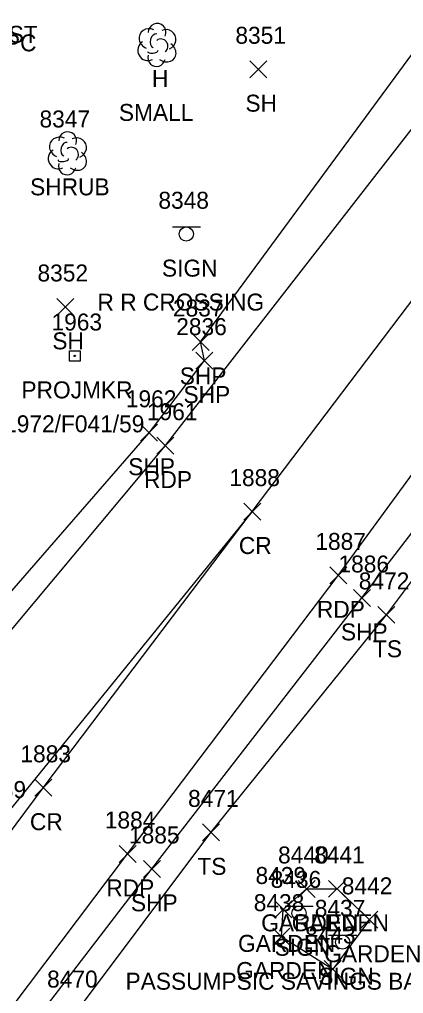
# Model space of a CAD drawing. Extents: x 1769141 to 1770911, y 735471 to 741449.
# Drawn here: x 1770474.3 to 1770519.5, y 736769.4 to 736884.2 of the extents above; entities that cross this region are included whole.
import ezdxf

# ---------------------------------------------------------------- set-up
doc = ezdxf.new("R2010")
doc.units = 0
for name, color, linetype in [('L_A', 7, 'Continuous'), ('L_C', 7, 'Continuous'), ('L_I', 7, 'Continuous'), ('L_TIC', 7, 'Continuous'), ('LAPB', 7, 'Continuous'), ('LELB', 7, 'Continuous'), ('LSH', 7, 'Continuous'), ('LTD', 7, 'Continuous'), ('P_A', 7, 'Continuous'), ('P_I', 7, 'Continuous'), ('P_TIC', 7, 'Continuous'), ('PET', 7, 'Continuous'), ('PRC', 7, 'Continuous'), ('PSP', 7, 'Continuous'), ('S_A', 7, 'Continuous'), ('S_C', 7, 'Continuous'), ('S_I', 7, 'Continuous'), ('SRM', 7, 'Continuous'), ('SSGN', 7, 'Continuous')]:
    doc.layers.add(name, color=color, linetype=linetype)

msp = doc.modelspace()

# ---------------------------------------------------------------- linework, layer by layer
at = {"layer": 'L_TIC'}
for points in [[(1770501.44, 736877.37), (1770503.44, 736879.37)], [(1770503.44, 736877.37), (1770501.44, 736879.37)], [(1770478.72, 736849.36), (1770480.72, 736851.36)], [(1770480.72, 736849.36), (1770478.72, 736851.36)], [(1770516.53, 736813.07), (1770518.53, 736815.07)], [(1770518.53, 736813.07), (1770516.53, 736815.07)], [(1770495.87, 736787.43), (1770497.87, 736789.43)], [(1770497.87, 736787.43), (1770495.87, 736789.43)], [(1770507.12, 736780.77), (1770509.12, 736782.77)], [(1770509.12, 736780.77), (1770507.12, 736782.77)], [(1770510.71, 736780.78), (1770512.71, 736782.78)], [(1770512.71, 736780.78), (1770510.71, 736782.78)], [(1770504.39, 736778.35), (1770506.39, 736780.35)], [(1770506.39, 736778.35), (1770504.39, 736780.35)], [(1770514.53, 736777.13), (1770516.53, 736779.13)], [(1770516.53, 736777.13), (1770514.53, 736779.13)], [(1770504.17, 736775.15), (1770506.17, 736777.15)], [(1770506.17, 736775.15), (1770504.17, 736777.15)], [(1770504.17, 736775.15), (1770506.17, 736777.15)], [(1770506.17, 736775.15), (1770504.17, 736777.15)], [(1770510.21, 736771.33), (1770512.21, 736773.33)], [(1770512.21, 736771.33), (1770510.21, 736773.33)], [(1770510.21, 736771.33), (1770512.21, 736773.33)], [(1770512.21, 736771.33), (1770510.21, 736773.33)]]:
    msp.add_lwpolyline(points, dxfattribs=at)
at = {"layer": 'LAPB'}
for points in [[(1770505.17, 736776.15), (1770505.39, 736779.35), (1770508.12, 736781.77), (1770511.71, 736781.78), (1770515.53, 736778.13), (1770511.21, 736772.33)], [(1770505.17, 736776.15), (1770511.21, 736772.33)]]:
    msp.add_lwpolyline(points, dxfattribs=at)
at = {"layer": 'LELB'}
msp.add_lwpolyline([(1770484.53, 736755.21), (1770481.19, 736760.34), (1770480.93, 736767.14), (1770496.87, 736788.43), (1770517.53, 736814.07), (1770527.89, 736827.88), (1770534.72, 736837.01), (1770542.14, 736846.79)], dxfattribs=at)
at = {"layer": 'LSH'}
msp.add_line((1770479.96, 736868.51), (1770479.96, 736868.51), dxfattribs=at)
msp.add_line((1770479.96, 736868.51), (1770479.96, 736868.51), dxfattribs=at)
msp.add_arc((1770480.01, 736869.94), 1.05, 335.5272, 180.9563, dxfattribs=at)
for centre, major_axis, ratio, start_param, end_param in [((1770479.17, 736869.17), (1.21, -0.51), 0.895232, 1.570796, 4.712389), ((1770479.75, 736868.96), (-0.208, -0.792), 0.645439, 3.141593, 6.283185), ((1770481, 736869.09), (-1.14, -0.48), 0.949671, 1.570796, 4.712389), ((1770478.88, 736867.8), (0.58, -1.04), 0.959034, 3.141593, 6.283185), ((1770480.46, 736868.34), (-0.5, 0.667), 0.989748, 3.141593, 6.283185), ((1770480.96, 736867.67), (-1.09, 0.79), 0.841452, 1.570796, 4.712389), ((1770479.5, 736867.76), (-0.625, -0.083), 0.423636, 0, 3.141593), ((1770479.96, 736867.01), (0.26, 1.06), 0.942809, 1.570796, 4.712389)]:
    msp.add_ellipse(centre, major_axis=major_axis, ratio=ratio, start_param=start_param, end_param=end_param, dxfattribs=at)
at = {"layer": 'LTD'}
msp.add_line((1770490.49, 736881.28), (1770490.49, 736881.28), dxfattribs=at)
msp.add_line((1770490.49, 736881.28), (1770490.49, 736881.28), dxfattribs=at)
msp.add_arc((1770490.54, 736882.72), 1.05, 335.5272, 180.9563, dxfattribs=at)
for centre, major_axis, ratio, start_param, end_param in [((1770489.7, 736881.95), (1.21, -0.51), 0.895232, 1.570796, 4.712389), ((1770490.28, 736881.74), (-0.208, -0.792), 0.645439, 3.141593, 6.283185), ((1770491.53, 736881.86), (-1.14, -0.48), 0.949671, 1.570796, 4.712389), ((1770489.41, 736880.57), (0.58, -1.04), 0.959034, 3.141593, 6.283185), ((1770490.99, 736881.11), (-0.5, 0.667), 0.989748, 3.141593, 6.283185), ((1770491.49, 736880.45), (-1.09, 0.79), 0.841452, 1.570796, 4.712389), ((1770490.03, 736880.53), (-0.625, -0.083), 0.423636, 0, 3.141593), ((1770490.49, 736879.78), (0.26, 1.06), 0.942809, 1.570796, 4.712389)]:
    msp.add_ellipse(centre, major_axis=major_axis, ratio=ratio, start_param=start_param, end_param=end_param, dxfattribs=at)
at = {"layer": 'P_TIC'}
for points in [[(1770494.66, 736845.23), (1770496.66, 736847.23)], [(1770496.66, 736845.23), (1770494.66, 736847.23)], [(1770495.1, 736843.03), (1770497.1, 736845.03)], [(1770497.1, 736843.03), (1770495.1, 736845.03)], [(1770488.6, 736834.53), (1770490.6, 736836.53)], [(1770490.6, 736834.53), (1770488.6, 736836.53)], [(1770490.51, 736833.01), (1770492.51, 736835.01)], [(1770492.51, 736833.01), (1770490.51, 736835.01)], [(1770500.73, 736825.24), (1770502.73, 736827.24)], [(1770502.73, 736825.24), (1770500.73, 736827.24)], [(1770500.73, 736825.24), (1770502.73, 736827.24)], [(1770502.73, 736825.24), (1770500.73, 736827.24)], [(1770510.85, 736817.72), (1770512.85, 736819.72)], [(1770512.85, 736817.72), (1770510.85, 736819.72)], [(1770513.63, 736815.06), (1770515.63, 736817.06)], [(1770515.63, 736815.06), (1770513.63, 736817.06)], [(1770476.14, 736792.69), (1770478.14, 736794.69)], [(1770478.14, 736792.69), (1770476.14, 736794.69)], [(1770486.07, 736784.89), (1770488.07, 736786.89)], [(1770488.07, 736784.89), (1770486.07, 736786.89)], [(1770488.93, 736783.13), (1770490.93, 736785.13)], [(1770490.93, 736783.13), (1770488.93, 736785.13)]]:
    msp.add_lwpolyline(points, dxfattribs=at)
at = {"layer": 'PET'}
for points in [[(1770273.03, 736558.89), (1770311.79, 736611.42), (1770334.28, 736642.03), (1770362.15, 736677.39), (1770395.21, 736718.71), (1770421.36, 736750.44), (1770447.16, 736781.61), (1770463.21, 736800.13), (1770491.51, 736834.01), (1770534.74, 736889.69), (1770564.34, 736930.52), (1770585.98, 736965.52), (1770596.03, 736985.79), (1770612.4, 737032.33), (1770618.9, 737068.16), (1770621.16, 737108.89), (1770618.7, 737143.12), (1770611.8, 737180.69), (1770603.3, 737213.06), (1770592.49, 737245.88), (1770581.45, 737278.47)], [(1770275.7, 736500.44), (1770293.46, 736523.99), (1770308.25, 736544.53), (1770339.6, 736585.99), (1770354.04, 736607.65), (1770377.09, 736638.85), (1770405.47, 736677.52), (1770433.08, 736714.63), (1770457.83, 736747.12), (1770487.07, 736785.89), (1770511.85, 736818.72), (1770532.14, 736846.48), (1770557.14, 736879.91), (1770576.72, 736906.62), (1770599.36, 736940.91), (1770615.19, 736970.36), (1770629.48, 737005.85), (1770638.55, 737040.65), (1770643.24, 737068.35), (1770645.29, 737100.93), (1770643.29, 737138.02), (1770637.48, 737178.2), (1770623.12, 737230.1), (1770608.3, 737274.14)]]:
    msp.add_lwpolyline(points, dxfattribs=at)
at = {"layer": 'PRC'}
for points in [[(1770275.21, 736520.72), (1770298.1, 736551.29), (1770321.86, 736584.28), (1770345.26, 736616.16), (1770366.92, 736646.03), (1770396.69, 736686.2), (1770425.3, 736724.73), (1770448.38, 736754.99), (1770477.14, 736793.69), (1770501.73, 736826.24), (1770522.96, 736854.3), (1770547.64, 736887.36), (1770567.26, 736914.2), (1770589.05, 736947.07), (1770604.65, 736975.91), (1770617.45, 737008.22), (1770626.95, 737044), (1770631.18, 737069.88), (1770632.95, 737101.22), (1770631.26, 737138.45), (1770625.46, 737176.49), (1770611.43, 737227.28), (1770596.59, 737271.46)], [(1770501.73, 736826.24), (1770471.87, 736789.48), (1770446.57, 736758.43), (1770420.81, 736726.65), (1770393.3, 736692.52), (1770366.57, 736659.29), (1770342, 736628.98), (1770314.02, 736593.33), (1770292.93, 736562.85), (1770274.26, 736537.5)]]:
    msp.add_lwpolyline(points, dxfattribs=at)
at = {"layer": 'PSP'}
for points in [[(1770309.31, 736612.5), (1770333.17, 736643.27), (1770360.37, 736678.09), (1770362.33, 736680.6), (1770393.29, 736720.83), (1770418.7, 736752.62), (1770444.15, 736783.41), (1770460.87, 736802.48), (1770489.6, 736835.53), (1770496.1, 736844.03), (1770495.66, 736846.23), (1770525.96, 736887.57), (1770531.67, 736892.21), (1770561.2, 736933.71), (1770581.74, 736967.46), (1770597.36, 737001.44), (1770607.31, 737032.41), (1770614.05, 737069.49), (1770616.45, 737108.68), (1770613.94, 737142.23), (1770607.29, 737180.12), (1770598.89, 737211.18), (1770587.45, 737244.33), (1770575.08, 737276.15)], [(1770340.14, 736567.06), (1770355.71, 736595.48), (1770384.34, 736632.07), (1770413.38, 736670.65), (1770426.21, 736690.9), (1770435.18, 736712.82), (1770460.13, 736745.31), (1770489.93, 736784.13), (1770514.63, 736816.06), (1770535.7, 736843.49), (1770560.97, 736877.11), (1770581.17, 736903.18), (1770605.6, 736937.84), (1770621.17, 736966.95), (1770635.97, 737003.98), (1770646.02, 737037.66), (1770650.84, 737066.81), (1770652.59, 737098.8), (1770650.92, 737139.65), (1770647.51, 737164.15), (1770640.68, 737197.77), (1770629.07, 737231.11), (1770614.09, 737275.47)]]:
    msp.add_lwpolyline(points, dxfattribs=at)
at = {"layer": 'SRM'}
msp.add_lwpolyline([(1770480.23, 736845.2), (1770481.48, 736845.2), (1770481.48, 736843.95), (1770480.23, 736843.95)], close=True, dxfattribs=at)
msp.add_circle((1770480.85, 736844.58), 0.0833, dxfattribs=at)
at = {"layer": 'SSGN'}
for p, q in [((1770492.33, 736859.78), (1770495.66, 736859.78)), ((1770493.97, 736858.95), (1770493.97, 736858.95)), ((1770505.59, 736779.74), (1770508.92, 736779.74)), ((1770507.24, 736778.91), (1770507.24, 736778.91)), ((1770510.72, 736776.33), (1770514.06, 736776.33)), ((1770512.37, 736775.5), (1770512.37, 736775.5))]:
    msp.add_line(p, q, dxfattribs=at)
for centre in [(1770493.97, 736858.95), (1770507.24, 736778.91), (1770512.37, 736775.5)]:
    msp.add_circle(centre, 0.833, dxfattribs=at)

# ---------------------------------------------------------------- texts
at = {"layer": 'L_A'}
for s, p in [('STPC ST', (1770465.19, 736881.48)), ('STPC', (1770469.21, 736880.48)), ('H', (1770489.93, 736876.28)), ('SH', (1770500.93, 736873.37)), ('SHRUB', (1770475.59, 736863.51)), ('SH', (1770478.21, 736845.36)), ('TS', (1770515.94, 736809.07)), ('TS', (1770495.28, 736783.43)), ('GARDEN', (1770502.79, 736776.77)), ('GARDEN', (1770506.38, 736776.78)), ('GARDEN', (1770500.06, 736774.35)), ('GARDEN', (1770510.2, 736773.13)), ('GARDEN', (1770499.84, 736771.15)), ('GARDEN', (1770499.84, 736771.15))]:
    msp.add_text(s, height=2, dxfattribs=at).set_placement(p)
at = {"layer": 'L_C'}
msp.add_text('SMALL', height=2, dxfattribs=at).set_placement((1770486.04, 736872.28))
at = {"layer": 'L_I'}
for s, p in [('8351', (1770499.75, 736881.37)), ('8347', (1770476.7, 736871.51)), ('8352', (1770476.46, 736853.36)), ('8472', (1770514.27, 736817.07)), ('8471', (1770494.18, 736791.43)), ('8440', (1770504.77, 736784.77)), ('8441', (1770509.02, 736784.78)), ('8439', (1770502.12, 736782.35)), ('8442', (1770512.27, 736781.13)), ('8438', (1770501.91, 736779.15)), ('8438', (1770501.91, 736779.15)), ('8443', (1770507.95, 736775.33)), ('8443', (1770507.95, 736775.33)), ('8470', (1770477.59, 736770.14))]:
    msp.add_text(s, height=2, dxfattribs=at).set_placement(p)
at = {"layer": 'P_A'}
for s, p in [('SHP', (1770493.2, 736841.23)), ('SHP', (1770493.64, 736839.03)), ('SHP', (1770487.14, 736830.53)), ('RDP', (1770489, 736829.01)), ('CR', (1770500.16, 736821.24)), ('CR', (1770500.16, 736821.24)), ('RDP', (1770509.34, 736813.72)), ('SHP', (1770512.17, 736811.06)), ('CR', (1770475.57, 736788.69)), ('RDP', (1770484.56, 736780.89)), ('SHP', (1770487.46, 736779.13))]:
    msp.add_text(s, height=2, dxfattribs=at).set_placement(p)
at = {"layer": 'P_I'}
for s, p in [('2837', (1770492.4, 736849.23)), ('2836', (1770492.79, 736847.03)), ('1962', (1770486.86, 736838.53)), ('1961', (1770489.34, 736837.01)), ('1888', (1770499.04, 736829.24)), ('1888', (1770499.04, 736829.24)), ('1887', (1770509.16, 736821.72)), ('1886', (1770511.88, 736819.06)), ('1883', (1770474.45, 736796.69)), ('1889', (1770469.17, 736792.48)), ('1884', (1770484.38, 736788.89)), ('1885', (1770487.23, 736787.13))]:
    msp.add_text(s, height=2, dxfattribs=at).set_placement(p)
at = {"layer": 'S_A'}
for s, p in [('SIGN', (1770491.11, 736853.93)), ('PROJMKR', (1770474.57, 736839.58)), ('SIGN', (1770504.37, 736773.89)), ('SIGN', (1770509.51, 736770.48))]:
    msp.add_text(s, height=2, dxfattribs=at).set_placement(p)
at = {"layer": 'S_C'}
for s, p in [('R R CROSSING', (1770483.52, 736849.93)), ('VT/1972/F041/59', (1770468.37, 736835.58)), ('PASSUMPSIC SAVINGS BANK', (1770486.82, 736769.89))]:
    msp.add_text(s, height=2, dxfattribs=at).set_placement(p)
at = {"layer": 'S_I'}
for s, p in [('8348', (1770490.69, 736861.93)), ('1963', (1770478.11, 736847.58)), ('8436', (1770503.9, 736781.89)), ('8437', (1770509.09, 736778.48))]:
    msp.add_text(s, height=2, dxfattribs=at).set_placement(p)

doc.saveas('drawing.dxf')
